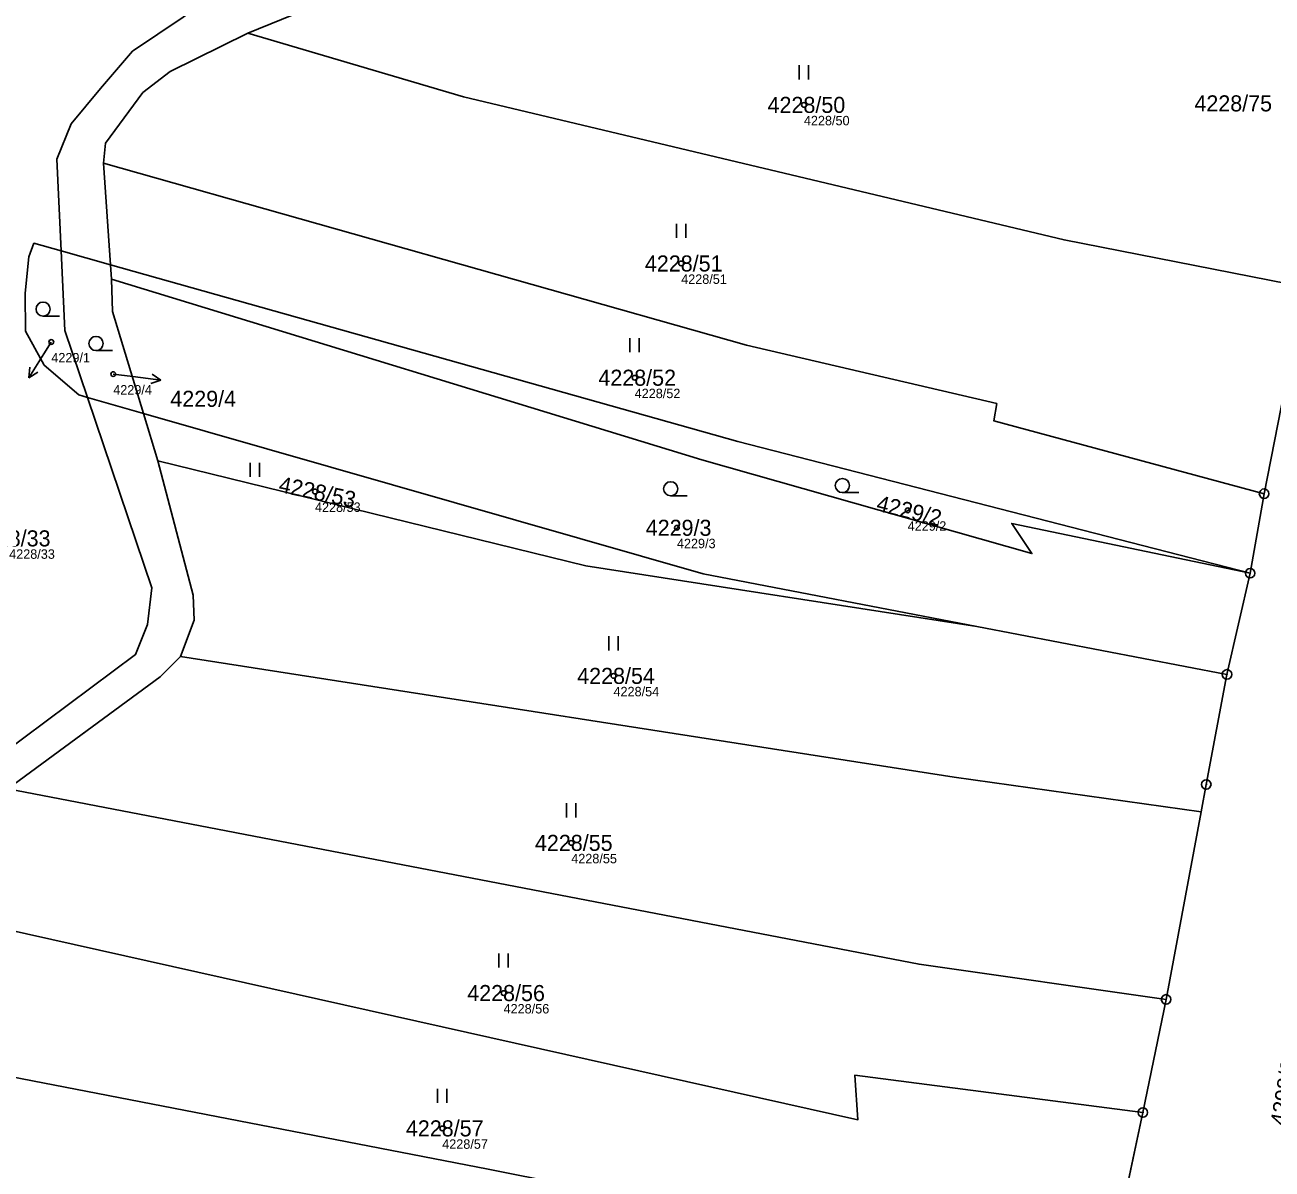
# Model space of a CAD drawing. Extents: x -739214 to -733252, y -1147612 to -1142842.
# Drawn here: x -736633.4 to -736501.5, y -1146892.7 to -1146771.7 of the extents above; entities that cross this region are included whole.
import ezdxf

# ---------------------------------------------------------------- set-up
doc = ezdxf.new("R2010")
doc.units = 0
for name, color, linetype in [('Definiční body', 7, 'Continuous'), ('Hranice parcel', 7, 'Continuous'), ('Parcelní čísla', 7, 'Continuous'), ('Polygon parcely', 7, 'Continuous'), ('Pop  PČ popisy', 7, 'Continuous'), ('Značky bodu BP', 7, 'Continuous'), ('Značky kultur', 7, 'Continuous')]:
    doc.layers.add(name, color=color, linetype=linetype)

msp = doc.modelspace()

# ---------------------------------------------------------------- linework, layer by layer
at = {"layer": 'Definiční body'}
for centre in [(-736550.99, -1146780.12), (-736563.97, -1146796.9), (-736630.6, -1146805.21), (-736624.05, -1146808.61), (-736568.89, -1146808.99), (-736602.71, -1146821.03), (-736540.01, -1146823.02), (-736564.42, -1146824.87), (-736571.13, -1146840.54), (-736575.6, -1146858.21), (-736582.76, -1146874.1), (-736589.25, -1146888.42)]:
    msp.add_circle(centre, 0.25, dxfattribs=at)
at = {"layer": 'Hranice parcel'}
for p, q in [((-736625.09, -1146786.3), (-736624.35, -1146797.04)), ((-736632.44, -1146794.76), (-736629.56, -1146795.57)), ((-736629.56, -1146795.57), (-736624.35, -1146797.04)), ((-736624.35, -1146797.04), (-736624.25, -1146798.55)), ((-736626.78, -1146811.07), (-736627.69, -1146810.81)), ((-736620.85, -1146812.77), (-736626.78, -1146811.07)), ((-736620.85, -1146812.77), (-736619.32, -1146817.78)), ((-736503.79, -1146829.68), (-736502.31, -1146821.26)), ((-736506.23, -1146840.38), (-736503.79, -1146829.68)), ((-736506.23, -1146840.38), (-736532.71, -1146835.3)), ((-736512.68, -1146874.77), (-736508.96, -1146854.94)), ((-736515.13, -1146886.74), (-736512.68, -1146874.77)), ((-736517.51, -1146897.85), (-736515.13, -1146886.74))]:
    msp.add_line(p, q, dxfattribs=at)
for points in [[(-736579.41, -1146757.89), (-736585.6, -1146761.84), (-736592.01, -1146765.26), (-736609.82, -1146772.52)], [(-736629.56, -1146795.57), (-736630.01, -1146785.87), (-736628.51, -1146782.13), (-736625.41, -1146778.39), (-736622, -1146774.44), (-736613.96, -1146769.04), (-736600.61, -1146763.59)], [(-736609.82, -1146772.52), (-736618.04, -1146776.58), (-736620.93, -1146778.82), (-736624.88, -1146784.16), (-736625.09, -1146786.3)], [(-736609.82, -1146772.52), (-736586.99, -1146779.25), (-736523.46, -1146794.4), (-736497.78, -1146799.46)], [(-736625.09, -1146786.3), (-736557.07, -1146805.53), (-736530.58, -1146811.72), (-736530.9, -1146813.54), (-736502.31, -1146821.26)], [(-736627.69, -1146810.81), (-736631.35, -1146807.65), (-736633.32, -1146804.08), (-736633.38, -1146800.04), (-736632.98, -1146796.2), (-736632.44, -1146794.76)], [(-736626.78, -1146811.07), (-736629.16, -1146804), (-736629.56, -1146795.57)], [(-736624.35, -1146797.04), (-736557.96, -1146815.73), (-736503.79, -1146829.68)], [(-736624.25, -1146798.55), (-736561.77, -1146817.68), (-736526.86, -1146827.6), (-736529, -1146824.4), (-736503.79, -1146829.68)], [(-736624.25, -1146798.55), (-736624.14, -1146801.97), (-736620.85, -1146812.77)], [(-736502.31, -1146821.26), (-736499.4, -1146806.54), (-736497.78, -1146799.46)], [(-736656.1, -1146862.51), (-736640.62, -1146852.37), (-736621.69, -1146838.29), (-736620.41, -1146835.09), (-736619.98, -1146831.24), (-736626.78, -1146811.07)], [(-736532.71, -1146835.3), (-736561.65, -1146829.75), (-736620.85, -1146812.77)], [(-736619.32, -1146817.78), (-736574.04, -1146828.89), (-736532.71, -1146835.3)], [(-736619.32, -1146817.78), (-736615.59, -1146831.99), (-736615.48, -1146834.66), (-736616.94, -1146838.5)], [(-736616.94, -1146838.5), (-736619.07, -1146840.64), (-736635.21, -1146852.5)], [(-736616.94, -1146838.5), (-736535.1, -1146851.27), (-736508.96, -1146854.94)], [(-736508.96, -1146854.94), (-736508.42, -1146852.03), (-736506.23, -1146840.38)], [(-736635.21, -1146852.5), (-736538.81, -1146871.05), (-736512.68, -1146874.77)], [(-736651.4, -1146863.79), (-736545.28, -1146887.5), (-736545.6, -1146882.8), (-736515.13, -1146886.74)], [(-736650.98, -1146879.81), (-736584.4, -1146892.72), (-736536.23, -1146902.34), (-736541.46, -1146894.97), (-736517.51, -1146897.85)]]:
    msp.add_lwpolyline(points, dxfattribs=at)
at = {"layer": 'Polygon parcely'}
for points in [[(-736640.62, -1146852.37), (-736621.69, -1146838.29), (-736620.41, -1146835.09), (-736619.98, -1146831.24), (-736626.78, -1146811.07), (-736627.69, -1146810.81), (-736631.35, -1146807.65), (-736633.32, -1146804.08), (-736633.38, -1146800.04), (-736632.98, -1146796.2), (-736632.44, -1146794.76), (-736629.56, -1146795.57), (-736630.01, -1146785.87), (-736628.51, -1146782.13), (-736625.41, -1146778.39), (-736622, -1146774.44), (-736613.96, -1146769.04), (-736600.61, -1146763.59), (-736634.36, -1146756.54)], [(-736590.25, -1146759.75), (-736600.61, -1146763.59), (-736613.96, -1146769.04), (-736622, -1146774.44), (-736625.41, -1146778.39), (-736628.51, -1146782.13), (-736630.01, -1146785.87), (-736629.56, -1146795.57), (-736624.35, -1146797.04)], [(-736624.35, -1146797.04), (-736625.09, -1146786.3), (-736624.88, -1146784.16), (-736620.93, -1146778.82), (-736618.04, -1146776.58), (-736609.82, -1146772.52), (-736592.01, -1146765.26)], [(-736499.4, -1146806.54), (-736502.31, -1146821.26), (-736503.79, -1146829.68), (-736506.23, -1146840.38), (-736508.42, -1146852.03), (-736508.96, -1146854.94), (-736512.68, -1146874.77), (-736515.13, -1146886.74), (-736517.51, -1146897.85), (-736520.97, -1146915.55), (-736522.08, -1146925.13), (-736524.58, -1146952.15), (-736499.2, -1146963.41)], [(-736635.21, -1146852.5), (-736619.07, -1146840.64), (-736616.94, -1146838.5), (-736615.48, -1146834.66), (-736615.59, -1146831.99), (-736619.32, -1146817.78), (-736620.85, -1146812.77), (-736626.78, -1146811.07), (-736619.98, -1146831.24), (-736620.41, -1146835.09), (-736621.69, -1146838.29), (-736640.62, -1146852.37)]]:
    msp.add_lwpolyline(points, dxfattribs=at)
for points in [[(-736586.99, -1146779.25), (-736523.46, -1146794.4), (-736497.78, -1146799.46), (-736494.72, -1146783.73), (-736494.08, -1146778.8), (-736495.18, -1146777.89), (-736499.73, -1146770.36), (-736579.41, -1146757.89), (-736585.6, -1146761.84), (-736592.01, -1146765.26), (-736609.82, -1146772.52)], [(-736530.9, -1146813.54), (-736502.31, -1146821.26), (-736499.4, -1146806.54), (-736497.78, -1146799.46), (-736523.46, -1146794.4), (-736586.99, -1146779.25), (-736609.82, -1146772.52), (-736618.04, -1146776.58), (-736620.93, -1146778.82), (-736624.88, -1146784.16), (-736625.09, -1146786.3), (-736557.07, -1146805.53), (-736530.58, -1146811.72)], [(-736503.79, -1146829.68), (-736502.31, -1146821.26), (-736530.9, -1146813.54), (-736530.58, -1146811.72), (-736557.07, -1146805.53), (-736625.09, -1146786.3), (-736624.35, -1146797.04), (-736557.96, -1146815.73)], [(-736629.16, -1146804), (-736629.56, -1146795.57), (-736632.44, -1146794.76), (-736632.98, -1146796.2), (-736633.38, -1146800.04), (-736633.32, -1146804.08), (-736631.35, -1146807.65), (-736627.69, -1146810.81), (-736626.78, -1146811.07)], [(-736626.78, -1146811.07), (-736620.85, -1146812.77), (-736624.14, -1146801.97), (-736624.25, -1146798.55), (-736624.35, -1146797.04), (-736629.56, -1146795.57), (-736629.16, -1146804)], [(-736503.79, -1146829.68), (-736557.96, -1146815.73), (-736624.35, -1146797.04), (-736624.25, -1146798.55), (-736561.77, -1146817.68), (-736526.86, -1146827.6), (-736529, -1146824.4)], [(-736624.14, -1146801.97), (-736620.85, -1146812.77), (-736561.65, -1146829.75), (-736532.71, -1146835.3), (-736506.23, -1146840.38), (-736503.79, -1146829.68), (-736529, -1146824.4), (-736526.86, -1146827.6), (-736561.77, -1146817.68), (-736624.25, -1146798.55)], [(-736532.71, -1146835.3), (-736561.65, -1146829.75), (-736620.85, -1146812.77), (-736619.32, -1146817.78), (-736574.04, -1146828.89)], [(-736508.96, -1146854.94), (-736508.42, -1146852.03), (-736506.23, -1146840.38), (-736532.71, -1146835.3), (-736574.04, -1146828.89), (-736619.32, -1146817.78), (-736615.59, -1146831.99), (-736615.48, -1146834.66), (-736616.94, -1146838.5), (-736535.1, -1146851.27)], [(-736616.94, -1146838.5), (-736619.07, -1146840.64), (-736635.21, -1146852.5), (-736538.81, -1146871.05), (-736512.68, -1146874.77), (-736508.96, -1146854.94), (-736535.1, -1146851.27)], [(-736545.6, -1146882.8), (-736515.13, -1146886.74), (-736512.68, -1146874.77), (-736538.81, -1146871.05), (-736635.21, -1146852.5), (-736651.4, -1146863.79), (-736545.28, -1146887.5)], [(-736541.46, -1146894.97), (-736517.51, -1146897.85), (-736515.13, -1146886.74), (-736545.6, -1146882.8), (-736545.28, -1146887.5), (-736651.4, -1146863.79), (-736654.82, -1146866.14), (-736650.98, -1146879.81), (-736584.4, -1146892.72), (-736536.23, -1146902.34)], [(-736520.97, -1146915.55), (-736517.51, -1146897.85), (-736541.46, -1146894.97), (-736536.23, -1146902.34), (-736584.4, -1146892.72), (-736650.98, -1146879.81), (-736647.63, -1146894.86), (-736615.98, -1146901.19), (-736529.06, -1146917.76), (-736528.5, -1146915.71)]]:
    msp.add_lwpolyline(points, close=True, dxfattribs=at)
at = {"layer": 'Pop  PČ popisy'}
for p, q in [((-736630.6, -1146805.21), (-736631.39, -1146806.45)), ((-736631.39, -1146806.45), (-736632.98, -1146809)), ((-736632.98, -1146809), (-736632.87, -1146807.88)), ((-736632.98, -1146809), (-736632.03, -1146808.41)), ((-736624.05, -1146808.61), (-736621.99, -1146808.87)), ((-736619.01, -1146809.24), (-736619.94, -1146808.62)), ((-736621.99, -1146808.87), (-736619.01, -1146809.24)), ((-736619.01, -1146809.24), (-736620.07, -1146809.61))]:
    msp.add_line(p, q, dxfattribs=at)
at = {"layer": 'Značky bodu BP'}
for centre, radius in [((-736502.31, -1146821.26), 0.5), ((-736502.31, -1146821.26), 0.0303), ((-736503.79, -1146829.68), 0.5), ((-736503.79, -1146829.68), 0.0303), ((-736506.23, -1146840.38), 0.5), ((-736506.23, -1146840.38), 0.0303), ((-736508.42, -1146852.03), 0.5), ((-736508.42, -1146852.03), 0.0303), ((-736512.68, -1146874.77), 0.5), ((-736512.68, -1146874.77), 0.0303), ((-736515.13, -1146886.74), 0.5), ((-736515.13, -1146886.74), 0.0303)]:
    msp.add_circle(centre, radius, dxfattribs=at)
at = {"layer": 'Značky kultur'}
for p, q in [((-736551.5, -1146777.42), (-736551.5, -1146775.92)), ((-736550.5, -1146777.42), (-736550.5, -1146775.92)), ((-736564.48, -1146794.2), (-736564.48, -1146792.7)), ((-736563.48, -1146794.2), (-736563.48, -1146792.7)), ((-736631.47, -1146802.48), (-736629.72, -1146802.48)), ((-736569.4, -1146806.29), (-736569.4, -1146804.79)), ((-736568.4, -1146806.29), (-736568.4, -1146804.79)), ((-736625.87, -1146806.12), (-736624.12, -1146806.12)), ((-736609.56, -1146819.49), (-736609.56, -1146817.99)), ((-736608.56, -1146819.49), (-736608.56, -1146817.99)), ((-736565.08, -1146821.49), (-736563.33, -1146821.49)), ((-736546.92, -1146821.15), (-736545.17, -1146821.15)), ((-736571.64, -1146837.84), (-736571.64, -1146836.34)), ((-736570.64, -1146837.84), (-736570.64, -1146836.34)), ((-736576.11, -1146855.51), (-736576.11, -1146854.01)), ((-736575.11, -1146855.51), (-736575.11, -1146854.01)), ((-736583.27, -1146871.4), (-736583.27, -1146869.9)), ((-736582.27, -1146871.4), (-736582.27, -1146869.9)), ((-736589.76, -1146885.72), (-736589.76, -1146884.22)), ((-736588.76, -1146885.72), (-736588.76, -1146884.22))]:
    msp.add_line(p, q, dxfattribs=at)
for centre in [(-736631.47, -1146801.73), (-736625.87, -1146805.37), (-736565.08, -1146820.74), (-736546.92, -1146820.4)]:
    msp.add_circle(centre, 0.75, dxfattribs=at)

# ---------------------------------------------------------------- texts
at = {"layer": 'Definiční body'}
for s, p in [('4228/50', (-736550.99, -1146782.28)), ('4228/51', (-736563.97, -1146799.06)), ('4229/1', (-736630.6, -1146807.37)), ('4229/4', (-736624.05, -1146810.77)), ('4228/52', (-736568.89, -1146811.15)), ('4228/53', (-736602.71, -1146823.19)), ('4229/2', (-736540.01, -1146825.18)), ('4228/33', (-736635.06, -1146828.15)), ('4229/3', (-736564.42, -1146827.03)), ('4228/54', (-736571.13, -1146842.7)), ('4228/55', (-736575.6, -1146860.37)), ('4228/56', (-736582.76, -1146876.26)), ('4228/57', (-736589.25, -1146890.58))]:
    msp.add_text(s, height=1, dxfattribs=at).set_placement(p)
at = {"layer": 'Parcelní čísla'}
for s, p in [('4228/50', (-736554.83, -1146780.97)), ('4228/75', (-736509.68, -1146780.81)), ('4228/51', (-736567.81, -1146797.75)), ('4228/52', (-736572.73, -1146809.84)), ('4229/4', (-736618.01, -1146812.07)), ('4229/3', (-736567.72, -1146825.72)), ('4228/33', (-736638.9, -1146826.84)), ('4228/54', (-736574.97, -1146841.39)), ('4228/55', (-736579.44, -1146859.06)), ('4228/56', (-736586.6, -1146874.95)), ('4228/57', (-736593.09, -1146889.27))]:
    msp.add_text(s, height=1.7, dxfattribs=at).set_placement(p)
for s, rotation, p in [('4228/53', 348, (-736606.64, -1146821.06)), ('4229/2', 346, (-736543.42, -1146823.04)), ('4298/6', 80, (-736500, -1146888.22))]:
    msp.add_text(s, height=1.7, rotation=rotation, dxfattribs=at).set_placement(p)

doc.saveas('drawing.dxf')
